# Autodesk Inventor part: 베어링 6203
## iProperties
IsCustomPart: 0
Company: 한국ATC센터
Created: 2014-08
Part Number: 베어링 6203
Material: 강, 연강
Description: 깊은 그루브 볼 베어링
Document SubType Name: Modeling
Standard: KS B 2023
Designer: KYOUNG IL JANG
Standards Organization: KS
Language: ko-KR
Size Designation: 6203 - 17 x 40 x 12
Categories: <MemberInstance><Categories><Category DisplayName="샤프트 부품" InternalName="7f7aeb1f-a693-4053-b835-cee3144e0d98" Mnemonic="SHFT"><Category DisplayName="베어링" Inter
Density: 1 g/cm^3
Author: KYOUNG IL JANG
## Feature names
1. IDS_ARRAYBALL[SIMPL:T] [Circular Pattern]
